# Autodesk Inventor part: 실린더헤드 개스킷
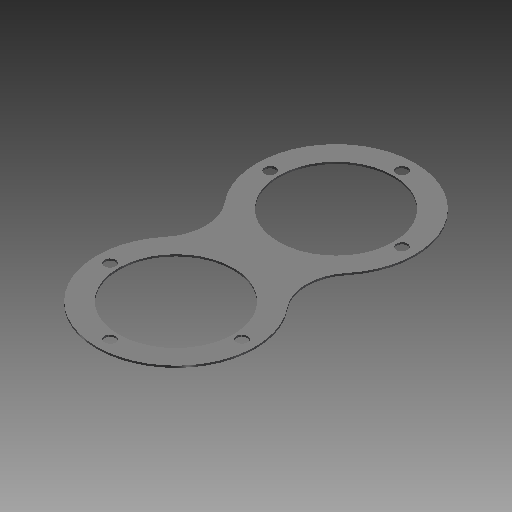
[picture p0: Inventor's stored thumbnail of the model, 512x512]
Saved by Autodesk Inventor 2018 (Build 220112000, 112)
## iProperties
Created: 2019-08
Part Number: 실린더헤드 개스킷
Material: 고무
Document SubType Name: Modeling
Designer: mduedu
Density: 0.93 g/cm^3
Appearance: 고무 - 검은색 - 버전 1.1
Mass: 5.11044 g
Surface Area: 119.346 cm^2
Volume: 5.49509 cm^3
Author: mduedu
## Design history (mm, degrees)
sketch "스케치1"
  geometry: L1 (0, 0)-(0, 85); C1 r 30.5 at (0, 85); C2 r 30.5 at (0, 0); A1 r 42 centre (0, 0) between (0, 42) and (-32.469, 26.642); A2 r 42 centre (0, 85) between (0, 43) and (32.469, 58.358); A3 r 25 centre (51.795, 42.5) between (32.469, 58.358) and (32.469, 26.642); A4 r 25 centre (-51.795, 42.5) between (-32.469, 26.642) and (-32.469, 58.358); A5 r 42 centre (0, 0) between (32.469, 26.642) and (0, 42); A6 r 42 centre (0, 0) between (-32.469, 26.642) and (32.469, 26.642); A7 r 42 centre (0, 85) between (-32.469, 58.358) and (0, 43); A8 r 42 centre (0, 85) between (32.469, 58.358) and (-32.469, 58.358); A9 r 25 centre (51.795, 42.5) between (32.469, 26.642) and (32.469, 58.358); A10 r 25 centre (-51.795, 42.5) between (-32.469, 58.358) and (-32.469, 26.642); 1 further point
  constraints: 20 point on circle, 12 centre point, 4 coincident, 4 tangent, 2 end point, 2 point on line, 1 vertical
  dimensions: "d1" = 84 diameter of A1; "d3" = 85 distance of L1.start L1.end; "d4" = 84 diameter of A2; "d5" = 50 diameter of A3; "d6" = 50 diameter of A4 (= d5); "d11" = 61 diameter of C1; "d12" = 61 diameter of C2
extrude "돌출2" new body sketch "스케치1" distance "d13" = 1; taper "d14" = 0 deg
sketch "스케치2"
  geometry: A1 r 35 centre (0, 0) between (-35, 0) and (0, 35); 2 further points
  constraints: 3 point on circle, 2 horizontal alignment, 1 centre point, 1 coincident, 1 vertical alignment
  dimensions: "d15" = 70 diameter of A1
hole "구멍1" sketch "스케치2" at (-35, 0), (0, 35), (35, 0) diameter "d16" = 6; stored, may be unused: countersink angle "d20" = 90 deg, drill point angle "d22" = 118 deg; dims "d17" = 6, "d18" = 4, "d19" = 2, "d21" = 8
node "작업 평면1"
mirror "대칭1"
node "솔리드2"
other parameters: "d23" = 42.5
